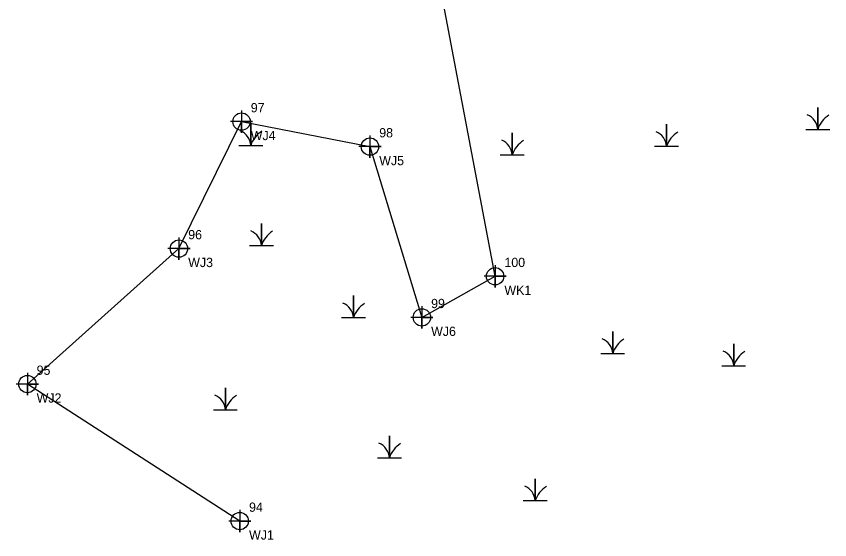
# Model space of a CAD drawing. Extents: x 2189822 to 2190837, y 387253 to 388663.
# Drawn here: x 2190286.1 to 2190505.5, y 387547.4 to 387688.6 of the extents above; entities that cross this region are included whole.
import ezdxf

# ---------------------------------------------------------------- set-up
doc = ezdxf.new("R2010")
doc.units = 0
for name, color, linetype in [('COGO Default Chain', 7, 'Continuous'), ('DTM Contours Major', 7, 'Continuous'), ('DTM Contours Minor', 7, 'Continuous'), ('Exist DTM Breakline Cogo Elevation', 7, 'Continuous'), ('Exist DTM Breakline Cogo Number', 7, 'Continuous')]:
    doc.layers.add(name, color=color, linetype=linetype)

msp = doc.modelspace()

# ---------------------------------------------------------------- linework, layer by layer
at = {"layer": 'DTM Contours Major'}
for points in [[(2190346.89, 387663.22), (2190346.89, 387657.22), (2190346.89, 387660.22), (2190349.89, 387660.22), (2190343.89, 387660.22)], [(2190381.54, 387656.46), (2190381.54, 387650.46), (2190381.54, 387653.46), (2190384.54, 387653.46), (2190378.54, 387653.46)], [(2190330.02, 387628.97), (2190330.02, 387622.97), (2190330.02, 387625.97), (2190333.02, 387625.97), (2190327.02, 387625.97)], [(2190415.3, 387621.48), (2190415.3, 387615.48), (2190415.3, 387618.48), (2190418.3, 387618.48), (2190412.3, 387618.48)], [(2190395.53, 387610.4), (2190395.53, 387604.4), (2190395.53, 387607.4), (2190398.53, 387607.4), (2190392.53, 387607.4)], [(2190289.14, 387592.41), (2190289.14, 387586.41), (2190289.14, 387589.41), (2190292.14, 387589.41), (2190286.14, 387589.41)], [(2190346.43, 387555.46), (2190346.43, 387549.46), (2190346.43, 387552.46), (2190349.43, 387552.46), (2190343.43, 387552.46)]]:
    msp.add_lwpolyline(points, dxfattribs=at)
for centre in [(2190346.89, 387660.22), (2190381.54, 387653.46), (2190330.02, 387625.97), (2190415.3, 387618.48), (2190395.53, 387607.4), (2190289.14, 387589.41), (2190346.43, 387552.46)]:
    msp.add_circle(centre, 2.34, dxfattribs=at)
at = {"layer": 'Exist DTM Breakline Cogo Elevation'}
for p, q in [((2190502.32, 387660.79), (2190502.32, 387660.79)), ((2190349.39, 387656.47), (2190349.39, 387656.47)), ((2190461.55, 387656.25), (2190461.55, 387656.25)), ((2190419.91, 387653.94), (2190419.91, 387653.94)), ((2190352.25, 387629.46), (2190352.25, 387629.46)), ((2190377.08, 387610.01), (2190377.08, 387610.01)), ((2190447.01, 387600.37), (2190447.01, 387600.37)), ((2190479.65, 387597.05), (2190479.65, 387597.05)), ((2190342.54, 387585.17), (2190342.54, 387585.17)), ((2190386.8, 387572.2), (2190386.8, 387572.2)), ((2190426.11, 387560.64), (2190426.11, 387560.64))]:
    msp.add_line(p, q, dxfattribs=at)
for points in [[(2190499.09, 387658.11), (2190502.32, 387658.11), (2190502.32, 387664.03), (2190502.32, 387658.11), (2190505.54, 387658.11)], [(2190346.17, 387653.8), (2190349.39, 387653.8), (2190349.39, 387659.72), (2190349.39, 387653.8), (2190352.62, 387653.8)], [(2190458.32, 387653.58), (2190461.55, 387653.58), (2190461.55, 387659.49), (2190461.55, 387653.58), (2190464.77, 387653.58)], [(2190416.69, 387651.26), (2190419.91, 387651.26), (2190419.91, 387657.18), (2190419.91, 387651.26), (2190423.14, 387651.26)], [(2190349.03, 387626.78), (2190352.25, 387626.78), (2190352.25, 387632.7), (2190352.25, 387626.78), (2190355.48, 387626.78)], [(2190373.86, 387607.34), (2190377.08, 387607.34), (2190377.08, 387613.26), (2190377.08, 387607.34), (2190380.31, 387607.34)], [(2190443.78, 387597.7), (2190447.01, 387597.7), (2190447.01, 387603.62), (2190447.01, 387597.7), (2190450.23, 387597.7)], [(2190476.42, 387594.37), (2190479.65, 387594.37), (2190479.65, 387600.29), (2190479.65, 387594.37), (2190482.87, 387594.37)], [(2190339.31, 387582.49), (2190342.54, 387582.49), (2190342.54, 387588.41), (2190342.54, 387582.49), (2190345.76, 387582.49)], [(2190383.58, 387569.53), (2190386.8, 387569.53), (2190386.8, 387575.45), (2190386.8, 387569.53), (2190390.03, 387569.53)], [(2190422.88, 387557.96), (2190426.11, 387557.96), (2190426.11, 387563.88), (2190426.11, 387557.96), (2190429.33, 387557.96)]]:
    msp.add_lwpolyline(points, dxfattribs=at)
for centre, radius, start, end in [((2190497.72, 387657.78), 4.61, 4.1403, 67.535), ((2190509.16, 387655.84), 7.21, 122.1274, 161.6222), ((2190344.79, 387653.46), 4.61, 4.1403, 67.535), ((2190356.23, 387651.52), 7.21, 122.1274, 161.6222), ((2190456.95, 387653.24), 4.61, 4.1403, 67.535), ((2190468.39, 387651.3), 7.21, 122.1274, 161.6222), ((2190415.31, 387650.93), 4.61, 4.1403, 67.535), ((2190426.75, 387648.99), 7.21, 122.1274, 161.6222), ((2190347.65, 387626.45), 4.61, 4.1403, 67.535), ((2190359.09, 387624.51), 7.21, 122.1274, 161.6222), ((2190372.48, 387607.01), 4.61, 4.1403, 67.535), ((2190383.93, 387605.07), 7.21, 122.1274, 161.6222), ((2190442.41, 387597.37), 4.61, 4.1403, 67.535), ((2190453.85, 387595.43), 7.21, 122.1274, 161.6222), ((2190475.05, 387594.04), 4.61, 4.1403, 67.535), ((2190486.49, 387592.1), 7.21, 122.1274, 161.6222), ((2190337.94, 387582.16), 4.61, 4.1403, 67.535), ((2190349.38, 387580.22), 7.21, 122.1274, 161.6222), ((2190382.2, 387569.19), 4.61, 4.1403, 67.535), ((2190393.64, 387567.26), 7.21, 122.1274, 161.6222), ((2190421.51, 387557.63), 4.61, 4.1403, 67.535), ((2190432.95, 387555.69), 7.21, 122.1274, 161.6222)]:
    msp.add_arc(centre, radius, start, end, dxfattribs=at)
at = {"layer": 'Exist DTM Breakline Cogo Number'}
msp.add_lwpolyline([(2190346.43, 387552.46), (2190289.14, 387589.41), (2190330.02, 387625.97), (2190346.89, 387660.22), (2190381.54, 387653.46), (2190395.53, 387607.4), (2190415.3, 387618.48), (2190397.15, 387714.42), (2190405.27, 387730.67)], dxfattribs=at)

# ---------------------------------------------------------------- texts
at = {"layer": 'COGO Default Chain'}
for s, p in [('WJ4', (2190349.39, 387655.22)), ('WJ5', (2190384.04, 387648.46)), ('WJ3', (2190332.52, 387620.97)), ('WK1', (2190417.8, 387613.48)), ('WJ6', (2190398.03, 387602.4)), ('WJ2', (2190291.64, 387584.41)), ('WJ1', (2190348.93, 387547.46))]:
    msp.add_text(s, height=2.5, dxfattribs=at).set_placement(p)
at = {"layer": 'DTM Contours Minor'}
for s, p in [('97', (2190349.39, 387662.72)), ('98', (2190384.04, 387655.96)), ('96', (2190332.52, 387628.47)), ('100', (2190417.8, 387620.98)), ('99', (2190398.03, 387609.9)), ('95', (2190291.64, 387591.91)), ('94', (2190348.93, 387554.96))]:
    msp.add_text(s, height=2.5, dxfattribs=at).set_placement(p)

doc.saveas('drawing.dxf')
